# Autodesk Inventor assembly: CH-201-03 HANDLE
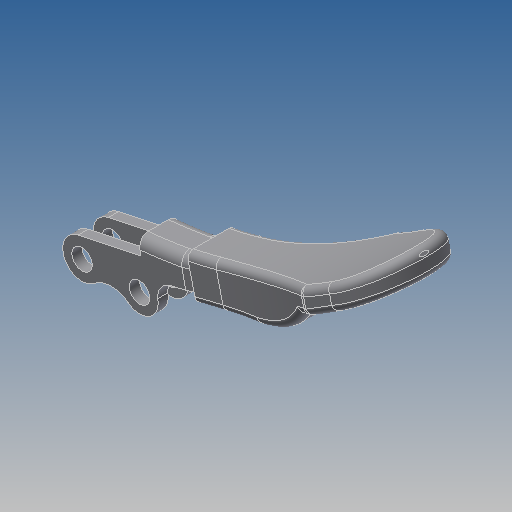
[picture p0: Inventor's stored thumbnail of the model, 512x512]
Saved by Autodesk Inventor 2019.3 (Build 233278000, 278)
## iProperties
Created: 2012-09
Part Number: CH-201-03 HANDLE
Material: Ogólny
Document SubType Name: Assembly
Designer: CADENGINEERING4
Author: CADENGINEERING4
Revision Number: ÈÎºÎ
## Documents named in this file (3)
- E:\STRONA\Horizontal toggle clamp\CH-201-AI\CH-201-03 HANDLE.iam
- E:\STRONA\Horizontal toggle clamp\CH-201-AI\CH-201-A-03.ipt
- E:\STRONA\Horizontal toggle clamp\CH-201-AI\CH-201-A-05.ipt
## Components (2 placed, 2 different names)
1. CH-201-A-03_13
2. CH-201-A-05_14
